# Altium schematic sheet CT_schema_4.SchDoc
size 400 x 230 mm
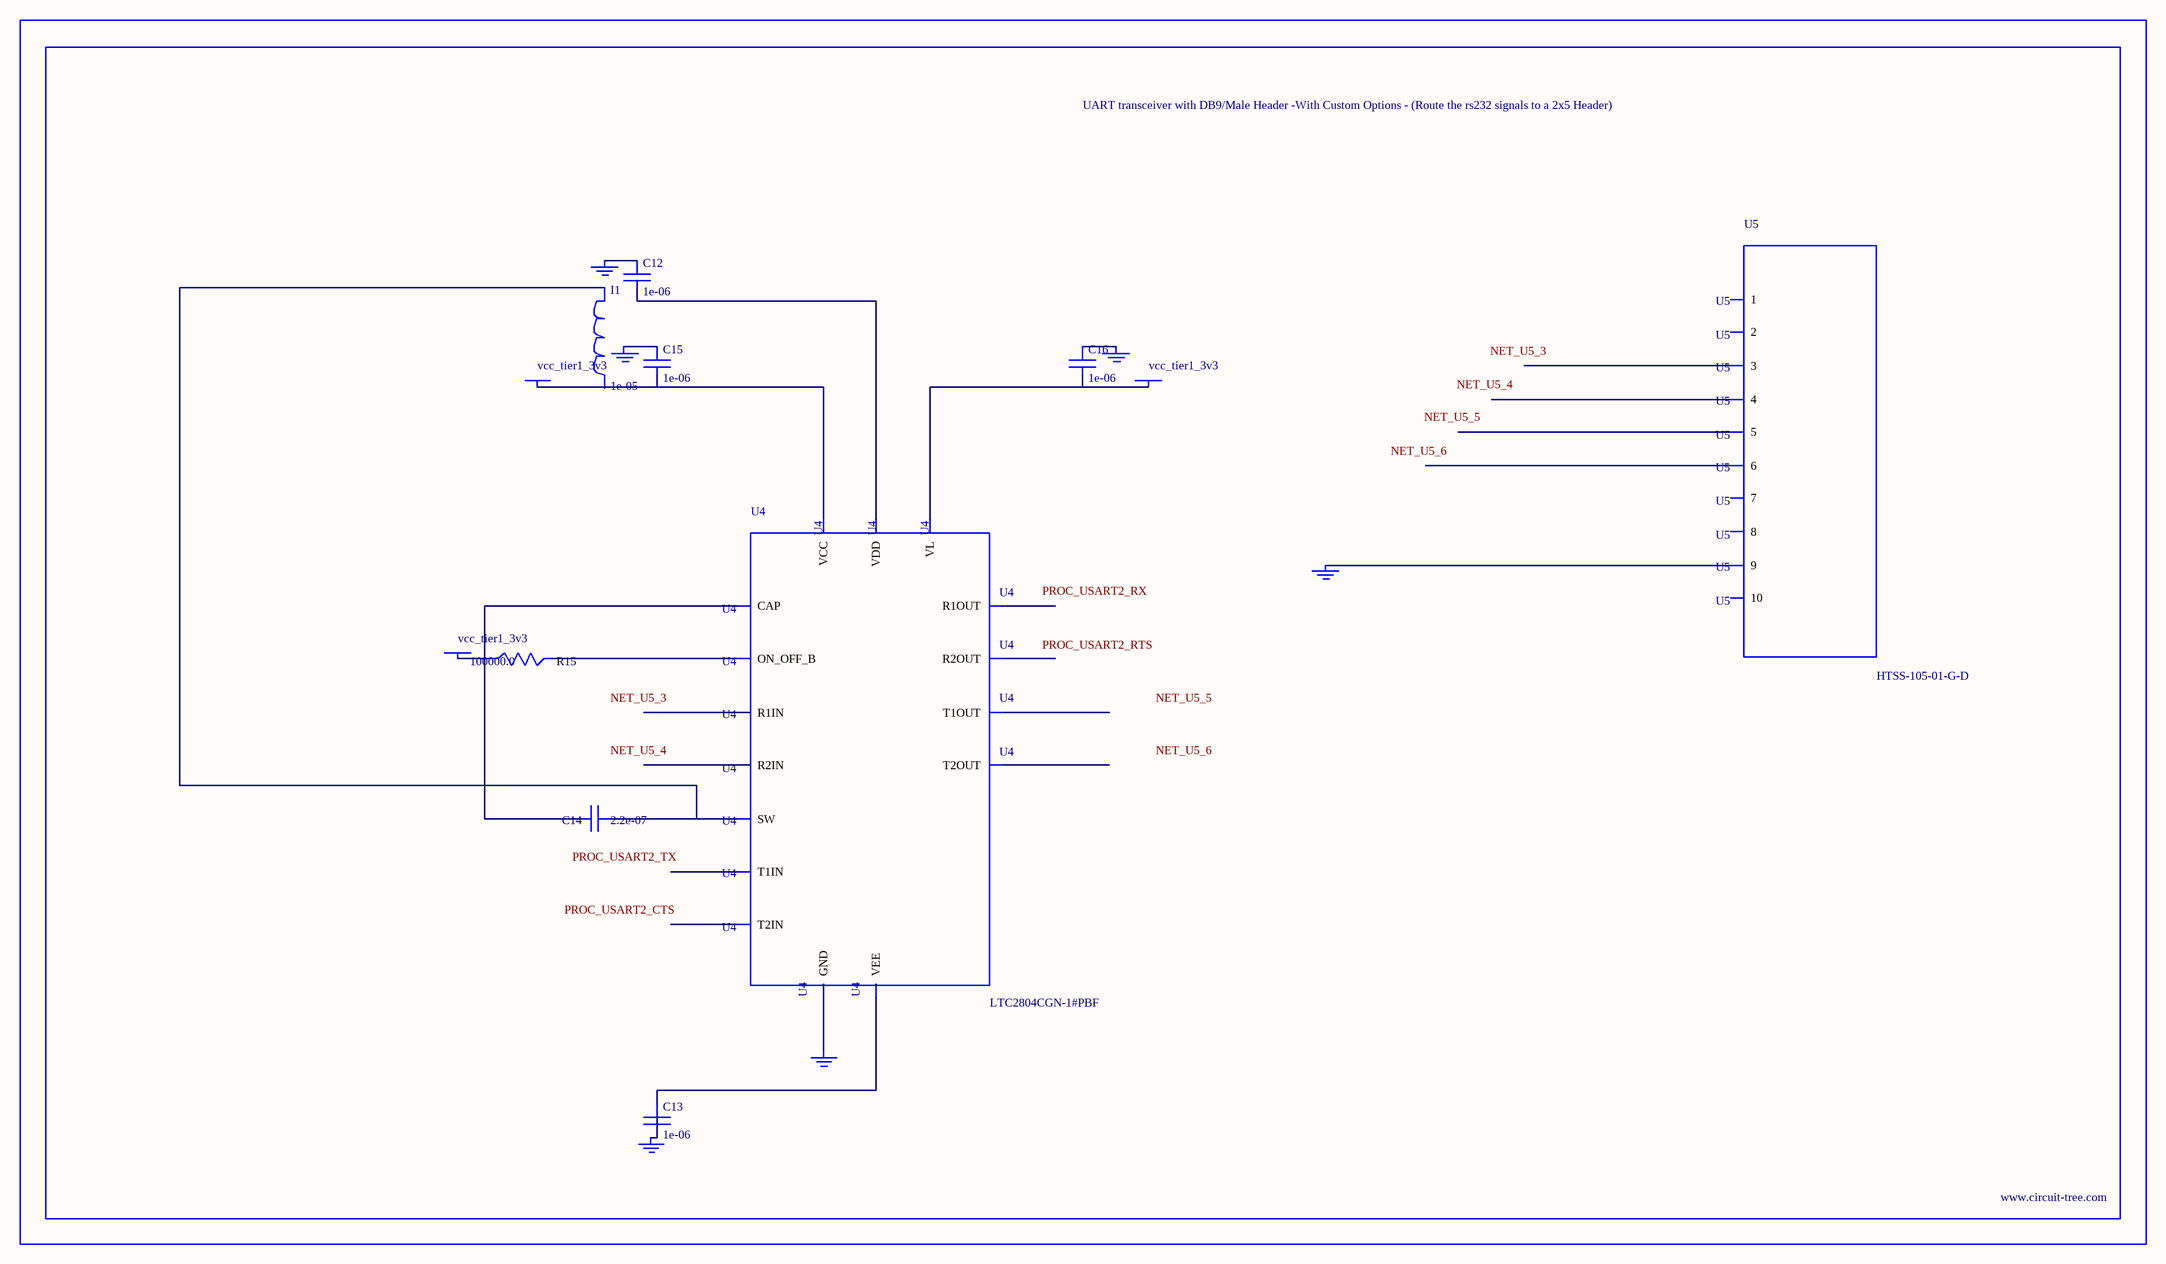
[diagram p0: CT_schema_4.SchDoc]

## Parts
BORDER3  (no value)
C12  1e-06  [C0603]
C13  1e-06  [C0603]
C14  2.2e-07  [C0603]
C15  1e-06  [C0603]
C16  1e-06  [C0603]
GND_INSTANCE_3_0  (no value)
GND_INSTANCE_3_1  (no value)
GND_INSTANCE_3_2  (no value)
GND_INSTANCE_3_3  (no value)
GND_INSTANCE_3_4  (no value)
GND_INSTANCE_3_5  (no value)
I1  1e-05  [L1210]
POWER_INSTANCE_3_0  vcc_tier1_3v3
POWER_INSTANCE_3_1  vcc_tier1_3v3
POWER_INSTANCE_3_2  vcc_tier1_3v3
R15  100000.0  [R0603]
U4  LTC2804CGN-1#PBF  [SSOP-16]
U5  HTSS-105-01-G-D  [HTSS-105-01-G-D]

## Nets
NetC12_1: C12.1 GND_INSTANCE_3_1.0(GND)
NetC12_2: C12.2 U4.6(VDD)
NetC13_1: C13.1 U4.9(VEE)
NetC13_2: C13.2 GND_INSTANCE_3_2.0(GND)
NetC14_1: C14.1 I1.1 U4.7(SW)
NetC14_2: C14.2 U4.10(CAP)
NetC15_1: C15.1 GND_INSTANCE_3_0.0(GND)
NetC15_2: C15.2 POWER_INSTANCE_3_0.0(PWR) U4.5(VCC)
NetC16_1: C16.1 GND_INSTANCE_3_3.0(GND)
NetC16_2: C16.2 POWER_INSTANCE_3_2.0(PWR) U4.12(VL)
NetGND_INSTANCE_3_4_0: GND_INSTANCE_3_4.0(GND) U4.8(GND)
NetGND_INSTANCE_3_5_0: GND_INSTANCE_3_5.0(GND) U5.9
NetPOWER_INSTANCE_3_1_0: POWER_INSTANCE_3_1.0(PWR) R15.1
NetR15_2: R15.2 U4.11(ON_OFF_B)

Not connected (* = marked no-connect by the designer): I1 2; U4 1(R1IN) 2(R2IN) 3(T1OUT) 4(T2OUT) 13(T2IN) 14(T1IN) 15(R2OUT) 16(R1OUT); U5 1 2 3 4 5 6 7 8 10

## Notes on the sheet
- Labels drawn without touching a wire or pin: NET_U5_3, NET_U5_4, NET_U5_5, NET_U5_6, PROC_USART2_CTS, PROC_USART2_RTS, PROC_USART2_RX, PROC_USART2_TX

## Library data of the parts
BORDER3 = BORDER_PAGE3
C12 C13 C15 C16 = C0603C105K3RACTU
C14 = C0603C224K3RAC
GND_INSTANCE_3_0-GND_INSTANCE_3_5 = GND
I1 = CBC3225T100MR
POWER_INSTANCE_3_0-POWER_INSTANCE_3_2 = PWR
R15 = RC0603JR-07100KL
